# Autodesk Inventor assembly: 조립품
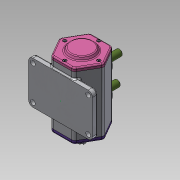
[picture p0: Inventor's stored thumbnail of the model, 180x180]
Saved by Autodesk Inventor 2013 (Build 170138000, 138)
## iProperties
Created: 2021-06
Part Number: 조립품
Document SubType Name: Assembly
Designer: cad21
Author: cad21
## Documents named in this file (11)
- C:\Users\cad21\Documents\Inventor\710606V1024\조립품.iam
- C:\Users\cad21\Documents\Inventor\710606V1024\본체.ipt
- C:\Users\cad21\Desktop\710606V1024\뒷커버.ipt
- C:\Users\cad21\Desktop\710606V1024\베어링 6203.ipt
- C:\Users\cad21\Desktop\710606V1024\베어링 6302.ipt
- C:\Users\cad21\Desktop\710606V1024\볼트 M4.ipt
- C:\Users\cad21\Desktop\710606V1024\부시.ipt
- C:\Users\cad21\Desktop\710606V1024\슬라이더.ipt
- C:\Users\cad21\Desktop\710606V1024\앞커버.ipt
- C:\Users\cad21\Desktop\710606V1024\오일실.ipt
- C:\Users\cad21\Desktop\710606V1024\편심축.ipt
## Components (10 placed, 3 different names)
1. 7-베어링 6203:1
2. 9-M4-소켓머리:1
3. 8-오일실:1
4. 9-M4-소켓머리:2
5. 9-M4-소켓머리:3
6. 9-M4-소켓머리:4
7. 9-M4-소켓머리:5
8. 9-M4-소켓머리:6
9. 9-M4-소켓머리:7
10. 9-M4-소켓머리:8
